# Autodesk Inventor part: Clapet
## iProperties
Shininess: 64.0
Length Units: 11269
Angle Units: 11279
Time Units: 11290
Mass Units: 11283
Length Display Precision: 3
Angle Display Precision: 2
Compacted: True
Part Number: Clapet
Document SubType Name: Modeling
Created: 2005-01
Material: Par défaut
Designer: Flavien MARTY
Density: 0.0
Volumn: 0.0
Area: 0.0
PropertySet Name: Model Information
Control State: 0
Master: False
Checked Out: False
Norme de conversion: STEP AP203
Nom du fichier: Clapet.STEP
Préprocesseur: SolidWorks 2001039
Postprocesseur: Build: Release: 6 RTM Build: 90b - Date: Tue 09/24/2002
Unités envoyées: MILLIMETERS
Incertitude: 0.0
Author: Flavien MARTY
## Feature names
1. Base1
